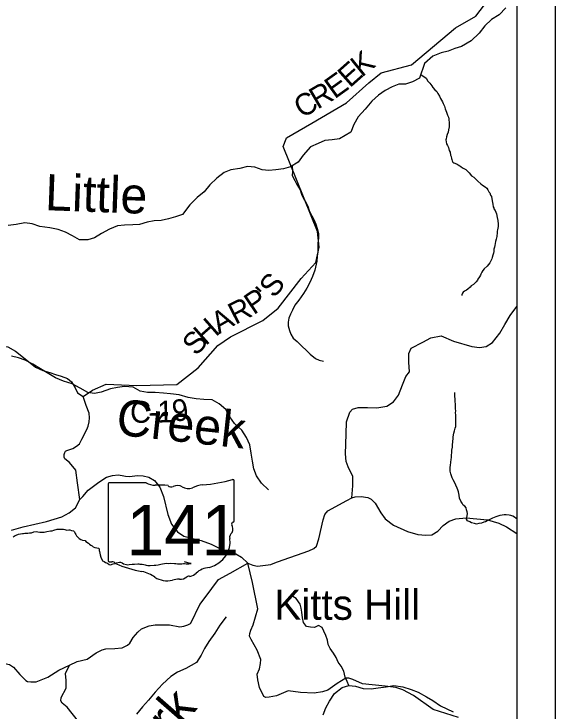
# Model space of a CAD drawing. Extents: x 0 to 34, y 0 to 22.
# Drawn here: x 7.584 to 9, y 17.398 to 19.223 of the extents above; entities that cross this region are included whole.
import ezdxf

# ---------------------------------------------------------------- set-up
doc = ezdxf.new("R2010")
doc.units = 0
for name, color, linetype in [('GM_X_County_Road', 7, 'Continuous'), ('GM_X_County_Road_Text', 7, 'Continuous'), ('GM_X_Minor_River', 7, 'Continuous'), ('GM_X_Minor_River_Text', 7, 'Continuous'), ('GM_X_State_Location', 7, 'Continuous'), ('GM_X_State_Route', 7, 'Continuous'), ('GM_X_State_Shield', 7, 'Continuous'), ('GM_X_Township_Road', 7, 'Continuous'), ('GM_X_Unincorporated_Text', 7, 'Continuous'), ('SH_Data', 7, 'Continuous')]:
    doc.layers.add(name, color=color, linetype=linetype)

msp = doc.modelspace()

# ---------------------------------------------------------------- linework, layer by layer
at = {"layer": 'GM_X_County_Road'}
for points in [[(7.7563, 17.9516), (7.75, 17.9954), (7.7459, 18.0284), (7.7294, 18.0492), (7.7175, 18.0582), (7.7158, 18.0632), (7.7155, 18.0696), (7.7174, 18.0748), (7.7192, 18.0783), (7.7226, 18.0803), (7.7382, 18.0854), (7.7473, 18.0914), (7.7552, 18.0973), (7.762, 18.1098), (7.7745, 18.1349), (7.7783, 18.1439), (7.7808, 18.1553), (7.7817, 18.1657), (7.7811, 18.1782), (7.7733, 18.1983), (7.7653, 18.2219), (7.7898, 18.2379), (7.8252, 18.2542), (7.9055, 18.2504), (8.0107, 18.2532), (8.0658, 18.2962), (8.1178, 18.3552), (8.151, 18.3776), (8.235, 18.4201), (8.2758, 18.4524), (8.3352, 18.5301), (8.3743, 18.5719), (8.3827, 18.6126), (8.3782, 18.6537), (8.2881, 18.876), (8.2966, 18.8955), (8.2975, 18.898), (8.3632, 18.9371), (8.4539, 18.9899), (8.5131, 19.0421), (8.5448, 19.0682), (8.6241, 19.0891), (8.7399, 19.1866), (8.7925, 19.2167), (8.824, 19.2581)], [(8.4685, 17.9564), (8.4704, 17.9878), (8.4708, 18.0118), (8.4587, 18.0376), (8.453, 18.0517), (8.4515, 18.0711), (8.4535, 18.1228), (8.4539, 18.1551), (8.463, 18.1802), (8.4702, 18.1885), (8.4847, 18.1927), (8.5093, 18.1931), (8.534, 18.1923), (8.5599, 18.1961), (8.5773, 18.2079), (8.5899, 18.2246), (8.6009, 18.2523), (8.6093, 18.2736), (8.6188, 18.2861), (8.6177, 18.3112), (8.6177, 18.334), (8.6234, 18.3477), (8.6538, 18.3633), (8.6747, 18.375), (8.7017, 18.3803), (8.7339, 18.3663), (8.7826, 18.3522), (8.8023, 18.3495), (8.8194, 18.3526), (8.8365, 18.3632), (8.8551, 18.3871), (8.8688, 18.4099), (8.8821, 18.4331), (8.9, 18.4569)], [(8.0843, 17.6958), (8.1193, 17.7424), (8.1499, 17.7597), (8.1964, 17.7853)], [(8.2039, 17.5873), (8.2, 17.594), (8.2009, 17.6016), (8.204, 17.6097), (8.21, 17.6242), (8.2218, 17.6657), (8.2079, 17.7348), (8.1964, 17.7853)], [(8.0464, 17.6279), (8.0473, 17.6284), (8.0701, 17.6769), (8.0843, 17.6958)], [(7.866, 17.564), (7.867, 17.5641), (7.874, 17.5671), (7.8815, 17.5709), (7.8874, 17.5757), (7.8964, 17.5913), (7.9083, 17.6047), (7.9182, 17.6136), (7.9383, 17.6215), (7.9539, 17.6245), (7.9915, 17.6241), (8.0178, 17.619), (8.0283, 17.6209), (8.039, 17.6241), (8.0464, 17.6279)], [(8.7476, 17.3814), (8.6809, 17.4025), (8.6293, 17.4389), (8.6015, 17.4544), (8.5835, 17.4598), (8.5554, 17.4637), (8.496, 17.4697), (8.4705, 17.4809), (8.4602, 17.4841), (8.4559, 17.4847), (8.4522, 17.4845), (8.4295, 17.4702), (8.4053, 17.4533), (8.3915, 17.4487), (8.3697, 17.445), (8.3343, 17.4466), (8.302, 17.4512), (8.2713, 17.4384), (8.2515, 17.4349), (8.2434, 17.4343), (8.2375, 17.4362), (8.2263, 17.4604), (8.2221, 17.48), (8.2206, 17.4946), (8.2262, 17.5091), (8.2296, 17.5225), (8.2298, 17.5335), (8.2208, 17.5581), (8.2049, 17.5857), (8.2039, 17.5873)], [(7.5153, 17.4745), (7.5203, 17.488), (7.5383, 17.5171), (7.5434, 17.5211), (7.5527, 17.523), (7.5599, 17.5233), (7.5721, 17.5199), (7.5831, 17.5133), (7.5993, 17.4944), (7.6154, 17.4786), (7.6196, 17.4761), (7.6284, 17.4748), (7.6424, 17.475), (7.6731, 17.4871), (7.7014, 17.5056), (7.7298, 17.5182), (7.7491, 17.5284), (7.7756, 17.534), (7.7991, 17.5506), (7.8152, 17.5584), (7.8244, 17.561), (7.8484, 17.562), (7.866, 17.564)]]:
    msp.add_lwpolyline(points, dxfattribs=at)
at = {"layer": 'GM_X_Minor_River'}
for points in [[(8.8709, 19.2387), (8.8534, 19.2205), (8.8337, 19.2077), (8.8162, 19.1911), (8.8018, 19.1721), (8.7805, 19.1525), (8.7555, 19.1374), (8.7373, 19.1321), (8.7199, 19.1253), (8.7024, 19.1208), (8.6805, 19.1118), (8.6585, 19.0929), (8.6455, 19.0542), (8.6273, 19.0452), (8.6083, 19.0391), (8.5909, 19.0384), (8.5735, 19.0317), (8.5553, 19.0226), (8.5378, 19.0098), (8.5204, 18.9939), (8.5029, 18.9734), (8.4847, 18.953), (8.4733, 18.9333), (8.4656, 18.9136), (8.4361, 18.8962), (8.4164, 18.8933), (8.3974, 18.891), (8.38, 18.8835), (8.3603, 18.8744)], [(8.6487, 19.0639), (8.6625, 19.0544), (8.6669, 19.0467), (8.6725, 19.0413), (8.6773, 19.0344), (8.6802, 19.0298), (8.6858, 19.024), (8.6907, 19.0197), (8.6936, 19.0147), (8.698, 19.0071), (8.7006, 19.0013), (8.7057, 18.9929), (8.7075, 18.9879), (8.7104, 18.981), (8.7122, 18.9745), (8.7159, 18.9657), (8.7166, 18.963), (8.7184, 18.9573), (8.7209, 18.9527), (8.722, 18.9485), (8.7223, 18.9458), (8.7233, 18.9382), (8.7231, 18.9268), (8.7215, 18.9189), (8.7199, 18.9136), (8.7175, 18.9068), (8.7159, 18.9011), (8.715, 18.8958), (8.7146, 18.8932), (8.7152, 18.8878), (8.7163, 18.8829), (8.7185, 18.8787), (8.7214, 18.8729), (8.7232, 18.8653), (8.7254, 18.8611), (8.7268, 18.8527), (8.7278, 18.8496), (8.7289, 18.8447), (8.7303, 18.8416), (8.731, 18.8382), (8.7329, 18.8351), (8.7355, 18.8332), (8.7381, 18.832), (8.7438, 18.8292), (8.7464, 18.8277), (8.7509, 18.8249), (8.7535, 18.823), (8.758, 18.8202), (8.7633, 18.8175), (8.7666, 18.8151), (8.7718, 18.8101), (8.7756, 18.8066), (8.7811, 18.7993), (8.7875, 18.7954), (8.7908, 18.7923), (8.7975, 18.7846), (8.8057, 18.7784), (8.8102, 18.7749), (8.817, 18.7698), (8.8214, 18.7667), (8.8244, 18.7625), (8.8266, 18.7575), (8.8292, 18.7548), (8.831, 18.7487), (8.8339, 18.7445), (8.8356, 18.7334), (8.837, 18.725), (8.838, 18.7182), (8.8395, 18.7155), (8.8402, 18.7128), (8.8435, 18.7086), (8.8453, 18.7036), (8.8472, 18.6994), (8.8489, 18.6895), (8.8499, 18.6823), (8.8509, 18.6727), (8.8507, 18.6663), (8.8495, 18.6576), (8.8486, 18.6538), (8.8486, 18.6507), (8.8473, 18.6405), (8.846, 18.6333), (8.844, 18.6269), (8.8432, 18.6223), (8.8423, 18.6166), (8.8418, 18.6125), (8.8402, 18.6068), (8.8394, 18.6007), (8.8389, 18.5969), (8.8373, 18.5913), (8.8357, 18.5852), (8.8345, 18.5822), (8.8318, 18.5769), (8.829, 18.5713), (8.8224, 18.5626), (8.8147, 18.5559), (8.8112, 18.551), (8.8085, 18.5473), (8.8054, 18.5416), (8.8046, 18.539)], [(8.3603, 18.8744), (8.3406, 18.8533), (8.3276, 18.8351), (8.3079, 18.8222), (8.289, 18.8177), (8.2693, 18.8148), (8.2511, 18.8133), (8.2337, 18.8149), (8.2148, 18.8218), (8.1951, 18.8233), (8.1747, 18.8181), (8.1512, 18.8144), (8.1338, 18.8076), (8.1148, 18.7932), (8.0966, 18.7758), (8.0814, 18.7569), (8.0632, 18.7425), (8.0442, 18.7229), (8.0252, 18.6979), (8.007, 18.6918), (7.9881, 18.6866), (7.9691, 18.6821), (7.9509, 18.6814), (7.9328, 18.6777), (7.9123, 18.6716), (7.8949, 18.6709), (7.8729, 18.6702), (7.8548, 18.668), (7.8343, 18.6597), (7.8131, 18.6477), (7.7949, 18.6371), (7.7774, 18.6311), (7.7555, 18.6319), (7.7374, 18.6418), (7.7185, 18.6517), (7.6996, 18.6586), (7.6776, 18.6625), (7.6519, 18.6663), (7.6315, 18.6732), (7.6126, 18.6756), (7.5898, 18.6718), (7.5686, 18.6689)], [(8.3125, 18.8252), (8.3132, 18.8105), (8.3121, 18.7995), (8.3189, 18.7867), (8.3246, 18.776), (8.3329, 18.7624), (8.3367, 18.7514), (8.342, 18.7396), (8.348, 18.7294), (8.3529, 18.7192), (8.3575, 18.7055), (8.3631, 18.6945), (8.3688, 18.6847), (8.3737, 18.6726), (8.3779, 18.6608), (8.3809, 18.6483), (8.3813, 18.6358), (8.379, 18.6229), (8.379, 18.6005), (8.3779, 18.5888), (8.3764, 18.5755), (8.3711, 18.552), (8.3654, 18.5357), (8.3586, 18.5202), (8.3506, 18.5046), (8.3415, 18.4914), (8.3298, 18.4739), (8.3192, 18.4607), (8.3128, 18.4478), (8.3078, 18.4371), (8.3037, 18.4262), (8.3014, 18.4163), (8.3018, 18.4061), (8.3048, 18.3939), (8.309, 18.3845), (8.3146, 18.3746), (8.3248, 18.3655), (8.3377, 18.3534), (8.3498, 18.342), (8.3589, 18.3325), (8.3729, 18.3208), (8.3827, 18.317), (8.3937, 18.3139), (8.3937, 18.3136)], [(8.8046, 18.539), (8.8022, 18.5345), (8.7983, 18.5285), (8.7968, 18.5258), (8.7933, 18.5213), (8.7863, 18.5146), (8.7806, 18.5113), (8.7775, 18.5079), (8.7721, 18.5027), (8.7683, 18.5001), (8.7626, 18.4975), (8.7595, 18.4949), (8.7579, 18.4915), (8.7559, 18.4874), (8.7557, 18.4862)], [(8.2501, 17.9777), (8.2319, 17.9944), (8.2191, 18.0142), (8.2116, 18.0324), (8.2079, 18.0522), (8.2049, 18.0735), (8.2012, 18.0947), (8.1922, 18.1145), (8.1801, 18.1335), (8.1613, 18.151), (8.1492, 18.1685), (8.1387, 18.1875), (8.1213, 18.202), (8.1024, 18.2127), (8.0805, 18.2135), (8.0608, 18.2151), (8.0396, 18.2189), (8.0162, 18.2258), (7.9935, 18.2289), (7.9753, 18.2305), (7.9533, 18.2321), (7.9337, 18.2321), (7.914, 18.2352), (7.8959, 18.2459), (7.8732, 18.2475), (7.855, 18.2453), (7.8368, 18.2415), (7.8126, 18.2332), (7.7944, 18.2295), (7.777, 18.2318), (7.7573, 18.2433), (7.7362, 18.2547), (7.7135, 18.2616), (7.6931, 18.2708), (7.6749, 18.2807), (7.6538, 18.2937), (7.6334, 18.3059), (7.6137, 18.3166), (7.5956, 18.3227), (7.5774, 18.3273)], [(8.9, 17.9012), (8.898, 17.9023), (8.8938, 17.9054), (8.8893, 17.9082), (8.8845, 17.9105), (8.8803, 17.9114), (8.872, 17.9123), (8.8671, 17.9123), (8.8614, 17.9109), (8.8553, 17.9099), (8.8446, 17.9063), (8.8359, 17.9034), (8.8297, 17.9), (8.8248, 17.8978), (8.8179, 17.8938), (8.8133, 17.8923), (8.8072, 17.8902), (8.8008, 17.8891), (8.7947, 17.8877), (8.789, 17.889), (8.7815, 17.8914), (8.777, 17.8937), (8.7706, 17.8961), (8.7684, 17.9007), (8.7688, 17.9049), (8.7697, 17.909), (8.7705, 17.9151), (8.7699, 17.9197), (8.7684, 17.9246), (8.767, 17.93), (8.7641, 17.935), (8.7599, 17.937), (8.7566, 17.9423), (8.7537, 17.9473), (8.75, 17.9557), (8.7487, 17.9638), (8.7469, 17.9718), (8.7455, 17.9771), (8.7441, 17.9821), (8.74, 17.9894), (8.7375, 17.9959), (8.7335, 18.0039), (8.7309, 18.0089), (8.7291, 18.0139), (8.7277, 18.0192), (8.7255, 18.0261), (8.7252, 18.031), (8.7257, 18.0364), (8.7262, 18.0413), (8.7271, 18.0496), (8.7283, 18.0565), (8.7288, 18.0618), (8.7293, 18.0694), (8.7298, 18.0735), (8.7303, 18.0815), (8.7312, 18.0891), (8.7316, 18.0952), (8.7322, 18.1028), (8.7335, 18.1122), (8.7335, 18.1164), (8.7352, 18.1255), (8.7372, 18.1316), (8.7388, 18.1384), (8.7401, 18.1433), (8.7406, 18.1498), (8.7403, 18.1593), (8.7404, 18.1638), (8.7401, 18.1691), (8.7402, 18.1733), (8.7399, 18.179), (8.74, 18.1844), (8.7397, 18.1889), (8.7399, 18.1961), (8.7392, 18.2007), (8.7386, 18.2091), (8.7383, 18.2163), (8.738, 18.2205), (8.7381, 18.2273), (8.7378, 18.2319)], [(7.5824, 17.8546), (7.5874, 17.8576), (7.5901, 17.859), (7.5962, 17.8612), (7.6015, 17.8619), (7.606, 17.863), (7.6087, 17.8629), (7.6129, 17.864), (7.6167, 17.8639), (7.6208, 17.8642), (7.6246, 17.8649), (7.6299, 17.8645), (7.636, 17.867), (7.6425, 17.868), (7.6466, 17.8672), (7.6515, 17.8664), (7.6553, 17.8663), (7.6595, 17.8666), (7.6633, 17.8666), (7.6667, 17.8673), (7.6705, 17.8683), (7.6796, 17.8697), (7.6838, 17.8704), (7.6888, 17.8714), (7.6968, 17.8743), (7.7024, 17.8746), (7.7134, 17.8744), (7.7176, 17.8732), (7.7225, 17.872), (7.7278, 17.8723), (7.7304, 17.8723), (7.7346, 17.871), (7.7395, 17.8698), (7.7425, 17.8671), (7.7443, 17.8633), (7.7461, 17.8602), (7.7476, 17.8568), (7.7513, 17.8533), (7.755, 17.8502), (7.7588, 17.8474)], [(7.7588, 17.8474), (7.7637, 17.8458), (7.7701, 17.845), (7.7723, 17.8423), (7.7791, 17.8376), (7.7821, 17.8349), (7.785, 17.8326), (7.7888, 17.831), (7.7914, 17.8283), (7.7955, 17.8267), (7.8061, 17.825), (7.8068, 17.8219), (7.8071, 17.8189), (7.8082, 17.8158), (7.81, 17.807), (7.8114, 17.8009), (7.8161, 17.7917), (7.8203, 17.7898), (7.8233, 17.7874), (7.8289, 17.7854), (7.8334, 17.7819), (7.8368, 17.7815), (7.844, 17.7833), (7.8482, 17.7843), (7.852, 17.7862), (7.86, 17.788), (7.8627, 17.7883), (7.8668, 17.7859), (7.8705, 17.784), (7.8785, 17.7816), (7.8822, 17.7811), (7.8857, 17.7822), (7.8933, 17.7832), (7.8993, 17.7827), (7.908, 17.7833), (7.9111, 17.7833), (7.9137, 17.7829), (7.9194, 17.7828), (7.9235, 17.7816), (7.9277, 17.7807), (7.9303, 17.7799), (7.9345, 17.7795), (7.9409, 17.7794), (7.9508, 17.78), (7.9549, 17.7799), (7.9618, 17.7809), (7.9686, 17.7831), (7.9724, 17.7838), (7.9781, 17.7844), (7.9823, 17.7851), (7.988, 17.785), (7.9933, 17.7853), (8.0043, 17.7844), (8.0077, 17.7843), (8.0122, 17.7839), (8.019, 17.7834), (8.0232, 17.7837), (8.0274, 17.7844), (8.0304, 17.7843), (8.0346, 17.7839), (8.0414, 17.7841), (8.0444, 17.7845), (8.0482, 17.7848), (8.0452, 17.7844), (8.0305, 17.7885)], [(8.46, 17.4654), (8.4563, 17.476), (8.451, 17.487), (8.4469, 17.5026), (8.4401, 17.5162), (8.4321, 17.5264), (8.4268, 17.5386), (8.4204, 17.5496), (8.4117, 17.5621), (8.4064, 17.5727), (8.4045, 17.5841), (8.4004, 17.5962), (8.3947, 17.6076), (8.3909, 17.6171), (8.3811, 17.6227), (8.3701, 17.6167), (8.3602, 17.6182), (8.3496, 17.6193), (8.3421, 17.6299), (8.3387, 17.6428), (8.3375, 17.6576), (8.3357, 17.6675), (8.3326, 17.6785), (8.3224, 17.6933), (8.3137, 17.6978)], [(8.1393, 17.6448), (8.1226, 17.6235), (8.1096, 17.6023), (8.0937, 17.5804), (8.0823, 17.5622), (8.0739, 17.5447), (8.0617, 17.5258), (8.0336, 17.5099), (8.0124, 17.5001), (7.9942, 17.4888), (7.973, 17.4691), (7.9532, 17.4479), (7.9357, 17.4267), (7.9206, 17.4093), (7.9046, 17.3904)], [(8.3928, 17.389), (8.4005, 17.4065), (8.4096, 17.4246), (8.4225, 17.4443), (8.443, 17.4602), (8.4604, 17.4655), (8.4778, 17.4632), (8.4975, 17.4578), (8.5187, 17.457), (8.5369, 17.4592), (8.5581, 17.4622), (8.5785, 17.4652), (8.602, 17.4621), (8.6232, 17.4552), (8.6421, 17.4475), (8.6632, 17.4353), (8.6806, 17.4262), (8.7002, 17.4125), (8.7335, 17.3964)]]:
    msp.add_lwpolyline(points, dxfattribs=at)
at = {"layer": 'GM_X_State_Route'}
for points in [[(7.5776, 17.8717), (7.6084, 17.8801), (7.6688, 17.8942), (7.7095, 17.907), (7.7282, 17.917), (7.745, 17.9305), (7.7563, 17.9516), (7.7643, 17.9603), (7.7782, 17.9761), (7.8064, 17.9978), (7.8263, 18.0101), (7.8415, 18.0148), (7.8567, 18.0169), (7.8673, 18.0149), (7.876, 18.0133), (7.8865, 18.012), (7.9074, 18.0148), (7.9222, 18.0139), (7.9373, 18.0107), (7.9516, 18.0018), (7.9662, 17.9846), (7.9757, 17.9598), (7.9865, 17.9126), (7.996, 17.8874), (8.0121, 17.8671), (8.0283, 17.8563), (8.0554, 17.8488), (8.074, 17.8448), (8.1, 17.8354), (8.1278, 17.821), (8.1475, 17.8143), (8.1648, 17.8096), (8.1795, 17.8014), (8.1964, 17.7853), (8.2092, 17.7798), (8.2216, 17.7774), (8.2562, 17.7823), (8.2626, 17.7846), (8.2739, 17.7885)], [(8.2739, 17.7885), (8.3559, 17.8173), (8.3692, 17.8236), (8.3761, 17.8296), (8.3816, 17.8489), (8.3928, 17.8992), (8.3975, 17.9128), (8.4056, 17.9226), (8.4548, 17.9494), (8.4685, 17.9564), (8.4773, 17.9594), (8.4928, 17.9603), (8.5098, 17.9571), (8.5189, 17.9532), (8.5294, 17.9428), (8.5438, 17.9168), (8.5554, 17.9012), (8.5772, 17.885), (8.6141, 17.8686), (8.6413, 17.8603), (8.6617, 17.8589), (8.6772, 17.8599), (8.6933, 17.8692), (8.7071, 17.8842), (8.7231, 17.8955), (8.7406, 17.9017), (8.7672, 17.9044), (8.8236, 17.8985), (8.853, 17.8902), (8.8733, 17.8805), (8.9, 17.8628)]]:
    msp.add_lwpolyline(points, dxfattribs=at)
at = {"layer": 'GM_X_State_Shield'}
for p, q in [((7.8304, 17.9922), (7.8304, 17.7921)), ((7.9302, 17.9957), (7.8337, 17.9957)), ((8.16, 17.896), (8.16, 18.0006)), ((8.16, 17.896), (8.16, 17.896))]:
    msp.add_line(p, q, dxfattribs=at)
for centre, major_axis, start_param, end_param in [((8.0426, 18.2685), (0.3495, 0), 4.814394, 5.042369), ((8.1564, 18.0011), (0.00367, 0), 6.141152, 7.989035), ((7.8342, 17.9927), (0.00382, 0), 1.712693, 3.28349), ((7.9532, 18.0189), (0.037, 0), 4.042523, 4.731795), ((7.9655, 17.8833), (0.133, 0), 1.404758, 1.657858), ((7.9956, 17.9937), (0.0107, 0), 3.836095, 5.185415), ((8.0113, 17.9706), (0.0222, 0), 0.950623, 2.079405), ((8.0872, 17.9346), (0.0703, 0), 1.699011, 2.107814), ((8.04, 18.0023), (0.0267, 0), 4.081561, 5.145723), ((8.1561, 17.8956), (0.00393, 0), 5.05454, 6.418171), ((8.1592, 17.8883), (0.00568, 0), 1.883978, 3.671073), ((8.123, 17.875), (0.0341, 0), 5.934695, 6.695948), ((8.1732, 17.8522), (0.0248, 0), 2.387724, 3.262537), ((8.0622, 17.8388), (0.0874, 0), 5.101752, 6.440018), ((7.8342, 17.7917), (0.00385, 0), 3.00124, 4.508301), ((7.8348, 17.8122), (0.0294, 0), 4.665946, 4.897461), ((7.8408, 17.7806), (0.0106, 0), 0.519207, 1.627899), ((7.9747, 17.9604), (0.2524, 0), 4.195997, 4.488961), ((8.099, 17.7359), (0.0479, 0), 1.647645, 2.488434), ((7.8994, 17.7022), (0.079, 0), 0.823519, 1.323587), ((7.9848, 17.7796), (0.0501, 0), 4.026481, 4.996735), ((8.0174, 17.7646), (0.0267, 0), 4.691044, 5.507374), ((8.0416, 17.7452), (0.00752, 0), 1.147584, 2.315152), ((8.0384, 17.7727), (0.0282, 0), 4.937069, 5.64225), ((8.0138, 17.7104), (0.0412, 0), 1.495662, 1.94098)]:
    msp.add_ellipse(centre, major_axis=major_axis, ratio=0.8, start_param=start_param, end_param=end_param, dxfattribs=at)
at = {"layer": 'GM_X_Township_Road'}
for points in [[(7.3446, 18.3224), (7.3577, 18.3221), (7.3765, 18.3175), (7.3969, 18.3146), (7.4082, 18.3146), (7.4559, 18.3303), (7.4825, 18.3368), (7.5007, 18.3482), (7.5174, 18.3512), (7.5478, 18.3531), (7.5679, 18.3512), (7.5877, 18.3405), (7.6089, 18.3234), (7.6401, 18.2983), (7.6598, 18.2896), (7.678, 18.2842), (7.6928, 18.2789), (7.7076, 18.2747), (7.7243, 18.2683), (7.735, 18.2599), (7.7445, 18.2439), (7.7505, 18.2314), (7.7653, 18.2219)], [(7.7449, 17.1907), (7.7425, 17.1979), (7.7436, 17.2158), (7.7535, 17.2375), (7.776, 17.2682), (7.7858, 17.2964), (7.7881, 17.3097), (7.7692, 17.3499), (7.7233, 17.4085), (7.7104, 17.4195), (7.7066, 17.4248), (7.7077, 17.4343), (7.721, 17.4583), (7.7207, 17.478), (7.7192, 17.497), (7.7298, 17.5182)]]:
    msp.add_lwpolyline(points, dxfattribs=at)
at = {"layer": 'SH_Data'}
for p, q in [((9, 21), (9, 14)), ((8.9, 20.9), (8.9, 14.1))]:
    msp.add_line(p, q, dxfattribs=at)

# ---------------------------------------------------------------- texts
at = {"layer": 'GM_X_County_Road_Text'}
for s, rotation, p in [('K', 38.7171, (8.494, 19.0553)), ('E', 41.6719, (8.4629, 19.0275)), ('E', 35.6256, (8.4232, 18.9987)), ('R', 30.4997, (8.3784, 18.9719)), ('C', 30.0879, (8.3376, 18.9483)), ('S', 50.9804, (8.265, 18.4767)), ('P', 34.0733, (8.2113, 18.4337)), ("'", 47.5197, (8.2541, 18.4647)), ('R', 27.1995, (8.1634, 18.4086)), ('A', 29.7834, (8.1206, 18.384)), ('H', 41.3998, (8.0856, 18.3528)), ('S', 48.1143, (8.0612, 18.3255)), ('C', 359.5746, (7.8877, 18.153)), ('1', 1.4547, (7.9598, 18.1532)), ('9', 8.5759, (8.0024, 18.1548)), ('-', 1.3403, (7.9363, 18.1526))]:
    msp.add_text(s, height=0.0568, rotation=rotation, dxfattribs=at).set_placement(p)
at = {"layer": 'GM_X_Minor_River_Text'}
for s, height, rotation, p in [('Little', 0.09469, 357.9213, (7.6644, 18.7092)), ('Creek', 0.09469, 353.7555, (7.8489, 18.1219)), ('Fork', 0.09473, 48.7821, (7.8987, 17.215))]:
    msp.add_text(s, height=height, rotation=rotation, dxfattribs=at).set_placement(p)
at = {"layer": 'GM_X_State_Location'}
for s in ['s', 'r']:
    msp.add_text(s, height=0.000189, dxfattribs=at).set_placement((7.9915, 17.8789))
msp.add_text('141', height=0.000189, rotation=0, dxfattribs=at).set_placement((7.9247, 17.8651))
at = {"layer": 'GM_X_State_Shield'}
msp.add_text('141', height=0.13184, dxfattribs=at).set_placement((7.879, 17.8062))
at = {"layer": 'GM_X_Unincorporated_Text'}
msp.add_text('Kitts Hill', height=0.07898, rotation=0, dxfattribs=at).set_placement((8.2655, 17.6373))

doc.saveas('drawing.dxf')
